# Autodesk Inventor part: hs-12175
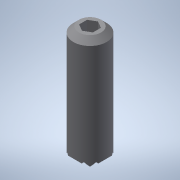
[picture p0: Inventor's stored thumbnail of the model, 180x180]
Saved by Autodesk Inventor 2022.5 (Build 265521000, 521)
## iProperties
Created: 2017-08
Part Number: hs-12175
Material: 一般
Document SubType Name: Modeling
Designer: imaocorp
Density: 1 g/cm^3
Appearance: 既定
Author: imaocorp
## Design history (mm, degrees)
node "hs-12175.x_t1"
node "hs-12175"
node "Base1"
